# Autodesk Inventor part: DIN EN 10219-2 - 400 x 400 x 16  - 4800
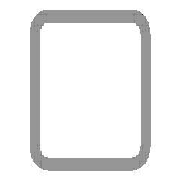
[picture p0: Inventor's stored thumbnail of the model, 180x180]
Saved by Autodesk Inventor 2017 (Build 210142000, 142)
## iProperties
IsCustomPart: 1
Created: 2017-11
Part Number: DIN EN 10219-2 - 400 x 400 x 16  - 4800
Material: Steel, Mild
Description: Cold formed welded structural hollow sections of non-alloy and fine grain structural steel
Document SubType Name: Modeling
Standard: DIN
Designer: iusti
Standard Revision: 2006-07
Standards Organization: DIN
Language: en-US
Size Designation: 400 x 400 x 16
Categories: <MemberInstance><Categories><Category DisplayName="Structural Shapes" InternalName="089c4875-fa83-4c05-b084-43b9cc11f5ed" Mnemonic="GRDR"><CategoryParameter Dis
Stock Number: 400 x 400 x 16
Density: 7.85 g/cm^3
Appearance: Semi-Polished
Mass: 884622 g
Surface Area: 141333 cm^2
Volume: 112691 cm^3
_CCFamilyMember: 142
_CCFamilyDisplayName: DIN EN 10219-2 (Square Hollow Section - Cold Formed) - Cold formed welded structural hollow sections of non-alloy and fine grain structural steel
_FrameMemberDoc: Frame Member File
_Version: 15.0.0
_GetPNFromCC: 1
G_L: 4800.000 mm
G_W: 400.000 mm
G_H: 400.000 mm
+3B88DE26-6118-40AC-AC7A-F683B1BCA643+CUTDETAIL1: Cut
Author: iusti
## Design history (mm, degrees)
node "Start plane"
node "End plane"
sketch "Sketch"
  geometry: L1 (-200, -152)-(-200, 152); L2 (-152, 200)-(152, 200); L3 (200, 152)-(200, -152); L4 (152, -200)-(-152, -200); L5 (-152, 184)-(152, 184); L6 (184, 152)-(184, -152); L7 (152, -184)-(-152, -184); L8 (-184, -152)-(-184, 152); L9 (0, 293.918)-(0, -293.918) reference; L10 (-293.918, 0)-(293.918, 0) reference; A1 r 48 centre (-152, -152) between (-200, -152) and (-152, -200); A2 r 48 centre (-152, 152) between (-152, 200) and (-200, 152); A3 r 48 centre (152, 152) between (200, 152) and (152, 200); A4 r 48 centre (152, -152) between (152, -200) and (200, -152); A5 r 32 centre (-152, 152) between (-152, 184) and (-184, 152); A6 r 32 centre (152, 152) between (184, 152) and (152, 184); A7 r 32 centre (152, -152) between (152, -184) and (184, -152); A8 r 32 centre (-152, -152) between (-184, -152) and (-152, -184)
  constraints: 16 end point, 16 point on circle, 8 centre point, 8 tangent, 4 parallel, 3 equal radius, 2 perpendicular, 7 other
  dimensions: "d7" = 48 radius of A1 (= G_IR); "d10" = 400 distance between parallel lines of L2 L4 (= G_H); "d11" = 400 distance between parallel lines of L1 L3 (= G_W); "d12" = 16 distance between parallel lines of L3 L6 (= G_T); "d15" = 200 distance between parallel lines of L2 L10 (= 0.5 x d10); "d16" = 200 distance between parallel lines of L9 L3 (= 0.5 x d11)
extrude "Body" new body sketch "Sketch" stored distance "d3" = 4800 (= G_L); taper "d4" = 0 deg
node "Driven Length"
  sketch "Sketch3"
    geometry: L1 (0, 0)-(10, 0) reference
    constraints: 2 end point, 1 horizontal
  workplane "Work Plane3"
  sketch "Sketch4"
    geometry: L1 (-2, 0)-(12, 0) reference; L2 (-2, 4800)-(12, 4800) reference
    dimensions: "d18" = 4800 distance between parallel lines of L1 L2 (derived)
workplane "Work Plane4"
split "Split1"
body "Solid1"
other parameters: "G_W" = 400 [user parameter; used in 1 equation term], "G_H" = 400 [user parameter; used in 1 equation term], "G_T" = 16 [user parameter; used in 1 equation term], "G_IR" = 48 [user parameter; used in 1 equation term], "G_L" = 4800 (= d18) [user parameter; used in 1 equation term], "G_OFFSET_START" = 0 [user parameter; used in 1 equation term], "d13" = 0 (computed from G_OFFSET_START), "d17" = 90 deg
